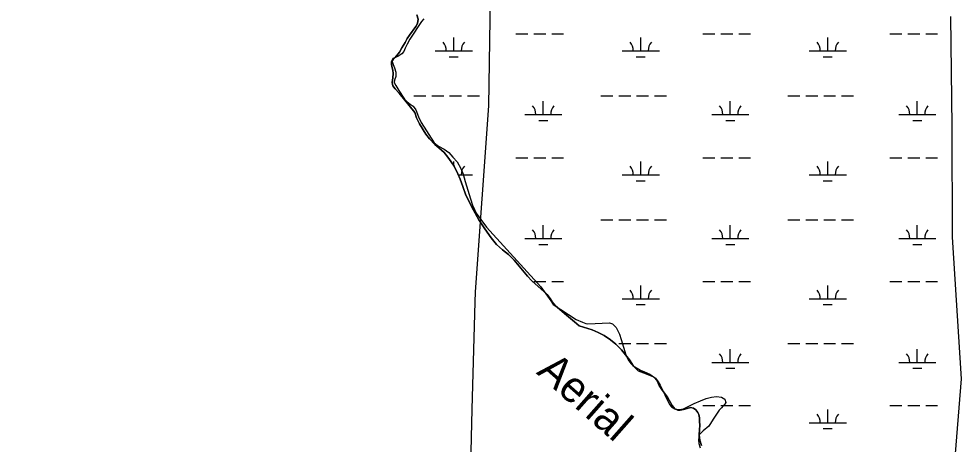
# Model space of a CAD drawing. Extents: x 3161564 to 3199464, y 849354 to 874788.
# Drawn here: x 3176490 to 3179019, y 859111 to 860252 of the extents above; entities that cross this region are included whole.
import ezdxf

# ---------------------------------------------------------------- set-up
doc = ezdxf.new("R2010")
doc.units = 0
for name, color, linetype in [('V-RIVR-IDEN', 7, 'Continuous'), ('V-ROAD-CNTR', 7, 'Continuous'), ('V-SITE-VEGE', 7, 'Continuous'), ('V-TOPO-BNDY', 7, 'Continuous'), ('V-TOPO-SHOR', 7, 'Continuous'), ('V-WETL-SWMP', 7, 'Continuous')]:
    doc.layers.add(name, color=color, linetype=linetype)

msp = doc.modelspace()

# ---------------------------------------------------------------- linework, layer by layer
at = {"layer": 'V-ROAD-CNTR'}
msp.add_spline([(3176879.1, 855651.9), (3176902.3, 855659.1), (3176934.1, 855667), (3176983.4, 855657.7), (3177040.7, 855639.1), (3177110.5, 855613.6), (3177170.6, 855601.8), (3177236.8, 855586.9), (3177274.8, 855573.5), (3177317.4, 855579.8), (3177362.6, 855595.7), (3177412, 855643.1), (3177451.7, 855679.2), (3177476.7, 855705.8), (3177478.3, 855737), (3177464.2, 855782.3), (3177430.8, 855833.4), (3177373, 855887.8), (3177287.8, 855954.8), (3177219.8, 855998.4), (3177153, 856039.4), (3177089.3, 856079.2), (3177023.4, 856134.3), (3176966.6, 856207.9), (3176895.2, 856290.1), (3176782.2, 856425.1), (3176693.2, 856545.3), (3176615.2, 856622.6), (3176543.9, 856726.5), (3176474.4, 856784.2), (3176414.4, 856823.6), (3176395.9, 856828), (3176350.8, 856806.2), (3176279.1, 856754.7), (3176211.6, 856707.4), (3176172.3, 856696.1), (3176141.1, 856702), (3176111.7, 856719.6), (3176032.6, 856777.4), (3175933.6, 856857.4), (3175839, 856930.3), (3175807.1, 856951.5), (3175770.1, 856958.7), (3175787.1, 856991.4), (3175795.1, 857040.7), (3175799.5, 857113.7), (3175810.8, 857206.9), (3175813.7, 857287.4), (3175807.8, 857386.8), (3175805.7, 857497.9), (3175801.9, 857543.6), (3175783.5, 857620.5), (3175760.2, 857716.1), (3175755.3, 857765.5), (3175754.5, 857815.6), (3175751.7, 857884.3), (3175756.3, 858015.5), (3175754.9, 858158.6), (3175753.1, 858270.8), (3175748.6, 858321.7), (3175736.5, 858372), (3175677.2, 858555.5), (3175602.2, 858747.1), (3175558.2, 858866.9), (3175502.5, 858986.2), (3175436.3, 859092.6), (3175371.2, 859185.1), (3175300.7, 859261.6), (3175219.1, 859367.2), (3175166.2, 859443.7), (3175175.3, 859507.1), (3175222, 859537.9), (3175285.3, 859568.3), (3175321.2, 859607.5), (3175310.3, 859667.2), (3175262.4, 859798.6), (3175224.6, 859877.9), (3175174.7, 859982), (3175144.8, 860115.4), (3175122.6, 860284.8), (3175088.4, 860568.6), (3175086.3, 860704.5), (3175072.2, 860854.5), (3175052.5, 860999.9), (3175047.5, 861166.8), (3175053.2, 861343.7), (3175066.7, 861550.4), (3175065.5, 861662.5), (3175040.2, 861767.8), (3175017.8, 861884.2), (3175008.4, 862033.9), (3174979.6, 862160.3), (3174952.1, 862274.6), (3174921.6, 862422.8), (3174897, 862525.5), (3174861.7, 862663.2), (3174841.1, 862738)], degree=3, dxfattribs=at)
at = {"layer": 'V-SITE-VEGE'}
for p, q in [((3177571.1, 860245.1), (3177540, 860197.8)), ((3177577.5, 860252.4), (3177571.1, 860245.1)), ((3177540, 860197.8), (3177532.6, 860184.6)), ((3177527.5, 860173.9), (3177523.8, 860164.9)), ((3177532.6, 860184.6), (3177527.5, 860173.9)), ((3177494.4, 860146.3), (3177491.7, 860140.8)), ((3177491.7, 860140.8), (3177494.8, 860129.8)), ((3177507.3, 860150.9), (3177494.4, 860146.3)), ((3177518.5, 860158.7), (3177507.3, 860150.9)), ((3177523.8, 860164.9), (3177518.5, 860158.7)), ((3177494.8, 860129.8), (3177498.7, 860120.6)), ((3177498.7, 860120.6), (3177502.1, 860109.3)), ((3177502, 860097.8), (3177498.1, 860087.4)), ((3177502.1, 860109.3), (3177502, 860097.8)), ((3177498.1, 860087.4), (3177497.5, 860081.7)), ((3177497.5, 860081.7), (3177501.7, 860073.7)), ((3177501.7, 860073.7), (3177510.3, 860060)), ((3177510.3, 860060), (3177525.8, 860037.2)), ((3177525.8, 860037.2), (3177532.3, 860030)), ((3177532.3, 860030), (3177540.4, 860023.6)), ((3177540.4, 860023.6), (3177548.2, 860018)), ((3177548.2, 860018), (3177555.5, 860007.8)), ((3177555.5, 860007.8), (3177562.9, 859989.1)), ((3177562.9, 859989.1), (3177569.9, 859974.2)), ((3177569.9, 859974.2), (3177605.1, 859920)), ((3177605.1, 859920), (3177616.2, 859910.8)), ((3177616.2, 859910.8), (3177631.7, 859902.9)), ((3177631.7, 859902.9), (3177644.6, 859893.3)), ((3177644.6, 859893.3), (3177655.3, 859881.5)), ((3177655.3, 859881.5), (3177666.5, 859868.6)), ((3177666.5, 859868.6), (3177676.7, 859850.8)), ((3177676.7, 859850.8), (3177682.7, 859835.4)), ((3177682.7, 859835.4), (3177688, 859816.1)), ((3177688, 859816.1), (3177702.7, 859769.4)), ((3177702.7, 859769.4), (3177708, 859752)), ((3177708, 859752), (3177712.9, 859740.6)), ((3177712.9, 859740.6), (3177717.6, 859730.9)), ((3177717.6, 859730.9), (3177745.9, 859693.1)), ((3177745.9, 859693.1), (3177891.2, 859533.3)), ((3177891.2, 859533.3), (3177918, 859495.9)), ((3177918, 859495.9), (3177924.6, 859485.6)), ((3177924.6, 859485.6), (3177986.4, 859445.7)), ((3177986.4, 859445.7), (3178002.8, 859438.7)), ((3178002.8, 859438.7), (3178012.5, 859434.7)), ((3178012.5, 859434.7), (3178017.7, 859433.4)), ((3178017.7, 859433.4), (3178075.5, 859436.2)), ((3178075.5, 859436.2), (3178083.7, 859433.9)), ((3178083.7, 859433.9), (3178093.6, 859424)), ((3178093.6, 859424), (3178102.5, 859406.3)), ((3178102.5, 859406.3), (3178107.2, 859391.7)), ((3178107.2, 859391.7), (3178119.4, 859351)), ((3178119.4, 859351), (3178125.6, 859337.3)), ((3178125.6, 859337.3), (3178132.7, 859327)), ((3178132.7, 859327), (3178139, 859320.8)), ((3178139, 859320.8), (3178158.7, 859309.1)), ((3178158.7, 859309.1), (3178169.7, 859305)), ((3178169.7, 859305), (3178183.5, 859298.9)), ((3178183.5, 859298.9), (3178198.8, 859288)), ((3178198.8, 859288), (3178206.4, 859277.9)), ((3178206.4, 859277.9), (3178211.5, 859269.3)), ((3178211.5, 859269.3), (3178236.7, 859217.1)), ((3178319.7, 859227.6), (3178334.9, 859233.3)), ((3178334.9, 859233.3), (3178349.5, 859237.3)), ((3178349.5, 859237.3), (3178362.4, 859238.6)), ((3178362.4, 859238.6), (3178375.8, 859237.2)), ((3178375.8, 859237.2), (3178385.6, 859231.7)), ((3178385.6, 859231.7), (3178387.5, 859222.7)), ((3178236.7, 859217.1), (3178242, 859211.2)), ((3178242, 859211.2), (3178250.9, 859205.8)), ((3178250.9, 859205.8), (3178262.6, 859203.7)), ((3178262.6, 859203.7), (3178273.8, 859205.3)), ((3178273.8, 859205.3), (3178302.5, 859219.9)), ((3178302.5, 859219.9), (3178319.7, 859227.6)), ((3178375.8, 859208.6), (3178370.3, 859202.2)), ((3178380.8, 859214.1), (3178375.8, 859208.6)), ((3178384.9, 859218.3), (3178380.8, 859214.1)), ((3178387.5, 859222.7), (3178384.9, 859218.3)), ((3178370.3, 859202.2), (3178353.7, 859178.1)), ((3178342.5, 859158.8), (3178327.4, 859146.8)), ((3178353.7, 859178.1), (3178342.5, 859158.8)), ((3178316.7, 859135.5), (3178314.3, 859122.3)), ((3178327.4, 859146.8), (3178316.7, 859135.5)), ((3178314.3, 859122.3), (3178315, 859112.3)), ((3178315, 859112.3), (3178319.1, 859101.1))]:
    msp.add_line(p, q, dxfattribs=at)
at = {"layer": 'V-TOPO-BNDY'}
for p, q in [((3177751.6, 860018.6), (3177757.6, 860399.3)), ((3177715.7, 859519.3), (3177751.6, 860018.6)), ((3177714.9, 859491.8), (3177715.7, 859519.3)), ((3177706.7, 859204.4), (3177714.9, 859491.8)), ((3177698.7, 858796.9), (3177706.7, 859204.4))]:
    msp.add_line(p, q, dxfattribs=at)
at = {"layer": 'V-TOPO-SHOR'}
for points in [[(3177558.4, 860263.6), (3177561.7, 860251.2), (3177560.3, 860239.7), (3177556, 860232.1), (3177539.2, 860208.5), (3177532.9, 860199.9), (3177527, 860188.8), (3177518, 860174.2), (3177511.8, 860162.6), (3177500.1, 860148.3), (3177494.9, 860143), (3177490.5, 860137.4), (3177490.1, 860130.9), (3177491, 860124.8), (3177493.9, 860115), (3177494.9, 860105.3), (3177494, 860093.9), (3177492.1, 860081.5), (3177494.3, 860072.9), (3177500.6, 860064.7), (3177511, 860052.8), (3177553.3, 860000.9), (3177557.8, 859986.7), (3177565.2, 859970.5), (3177582.9, 859943.3), (3177592.8, 859930.6), (3177606.9, 859915.4), (3177617.3, 859906), (3177625.1, 859899.9), (3177631.7, 859894.1), (3177642.1, 859881.1), (3177650.8, 859868.4), (3177658.4, 859856.9), (3177668.5, 859836), (3177674.4, 859821.8), (3177681.6, 859802.3), (3177689.9, 859779), (3177710.8, 859738.5), (3177724.6, 859712.7), (3177741.4, 859689.2), (3177758.2, 859664.5), (3177772.6, 859647.1), (3177788.2, 859632.3)], [(3177788.2, 859632.3), (3177804.4, 859619.8), (3177819.5, 859605.1), (3177855.1, 859562.1), (3177867.3, 859549.4), (3177908, 859513), (3177916.4, 859502.1), (3177921.7, 859493.1), (3177930.1, 859483.2), (3177942.3, 859472.1), (3177960.3, 859457.5), (3177981.9, 859439.1), (3177993.9, 859428.7), (3178028.7, 859417.3), (3178045.2, 859410.9), (3178061, 859402.2), (3178078.7, 859390.6), (3178092.6, 859379.2), (3178107.9, 859364.2), (3178129.1, 859337.6), (3178140.4, 859320.3), (3178152.9, 859308.1), (3178174.1, 859299.2), (3178193.5, 859292), (3178203.8, 859280.8), (3178208.8, 859268.3), (3178217.7, 859254.5), (3178231.1, 859236.8), (3178243.6, 859214.8), (3178251.2, 859205.9), (3178258.9, 859201.7), (3178265.1, 859202.2), (3178274.6, 859204), (3178284.5, 859206.7), (3178293.3, 859208.9), (3178301.3, 859207.7), (3178307.3, 859203.4), (3178312.7, 859195.5), (3178315.1, 859190.9), (3178317, 859181.4), (3178317, 859171.4), (3178318.1, 859162.1), (3178317, 859149.3), (3178316.7, 859136.2), (3178318.5, 859122), (3178322.5, 859106.9)]]:
    msp.add_lwpolyline(points, dxfattribs=at)
at = {"layer": 'V-WETL-SWMP'}
for p, q in [((3177561.7, 860251.2), (3177558.4, 860263.6)), ((3177560.3, 860239.7), (3177561.7, 860251.2)), ((3178991, 860258.3), (3178994.1, 859963.6)), ((3177539.2, 860208.5), (3177556, 860232.1)), ((3177556, 860232.1), (3177560.3, 860239.7)), ((3177527, 860188.8), (3177532.9, 860199.9)), ((3177532.9, 860199.9), (3177539.2, 860208.5)), ((3177657.5, 860166.1), (3177657.5, 860202.1)), ((3177824.5, 860212.5), (3177856.5, 860212.5)), ((3177872.5, 860212.5), (3177904.5, 860212.5)), ((3177920.5, 860212.5), (3177952.5, 860212.5)), ((3178159.4, 860166.1), (3178159.4, 860202.1)), ((3178326.5, 860212.5), (3178358.5, 860212.5)), ((3178374.5, 860212.5), (3178406.5, 860212.5)), ((3178422.5, 860212.5), (3178454.5, 860212.5)), ((3178661.3, 860166.1), (3178661.3, 860202.1)), ((3178828.4, 860212.5), (3178860.4, 860212.5)), ((3178876.4, 860212.5), (3178908.4, 860212.5)), ((3178924.4, 860212.5), (3178956.4, 860212.5)), ((3177511.8, 860162.6), (3177518, 860174.2)), ((3177518, 860174.2), (3177527, 860188.8)), ((3177607.5, 860166.1), (3177707.5, 860166.1)), ((3178109.4, 860166.1), (3178209.4, 860166.1)), ((3178611.3, 860166.1), (3178711.3, 860166.1)), ((3177490.5, 860137.4), (3177494.9, 860143)), ((3177494.9, 860143), (3177500.1, 860148.3)), ((3177500.1, 860148.3), (3177511.8, 860162.6)), ((3177645.5, 860150.7), (3177669.5, 860150.7)), ((3178147.4, 860150.7), (3178171.4, 860150.7)), ((3178649.3, 860150.7), (3178673.3, 860150.7)), ((3177490.1, 860130.9), (3177490.5, 860137.4)), ((3177491, 860124.8), (3177490.1, 860130.9)), ((3177493.9, 860115), (3177491, 860124.8)), ((3177494.9, 860105.3), (3177493.9, 860115)), ((3177492.1, 860081.5), (3177494, 860093.9)), ((3177494, 860093.9), (3177494.9, 860105.3)), ((3177494.3, 860072.9), (3177492.1, 860081.5)), ((3177500.6, 860064.7), (3177494.3, 860072.9)), ((3177511, 860052.8), (3177500.6, 860064.7)), ((3177553.3, 860000.9), (3177511, 860052.8)), ((3177550.6, 860046), (3177582.6, 860046)), ((3177598.6, 860046), (3177630.6, 860046)), ((3177646.6, 860046), (3177678.6, 860046)), ((3177694.6, 860046), (3177726.6, 860046)), ((3178052.5, 860046), (3178084.5, 860046)), ((3178100.5, 860046), (3178132.5, 860046)), ((3178148.5, 860046), (3178180.5, 860046)), ((3178196.5, 860046), (3178228.5, 860046)), ((3178554.5, 860046), (3178586.5, 860046)), ((3178602.5, 860046), (3178634.5, 860046)), ((3178650.5, 860046), (3178682.5, 860046)), ((3178698.5, 860046), (3178730.5, 860046)), ((3177898, 859995.3), (3177898, 860031.3)), ((3178399.9, 859995.3), (3178399.9, 860031.3)), ((3178901.8, 859995.3), (3178901.8, 860031.3)), ((3177557.8, 859986.7), (3177553.3, 860000.9)), ((3177848, 859995.3), (3177948, 859995.3)), ((3178349.9, 859995.3), (3178449.9, 859995.3)), ((3178851.8, 859995.3), (3178951.8, 859995.3)), ((3177565.2, 859970.5), (3177557.8, 859986.7)), ((3177582.9, 859943.3), (3177565.2, 859970.5)), ((3177886, 859979.8), (3177910, 859979.8)), ((3178387.9, 859979.8), (3178411.9, 859979.8)), ((3178889.8, 859979.8), (3178913.8, 859979.8)), ((3178994.1, 859963.6), (3178995.4, 859666.4)), ((3177592.8, 859930.6), (3177582.9, 859943.3)), ((3177606.9, 859915.4), (3177592.8, 859930.6)), ((3177617.3, 859906), (3177606.9, 859915.4)), ((3177625.1, 859899.9), (3177617.3, 859906)), ((3177631.7, 859894.1), (3177625.1, 859899.9)), ((3177642.1, 859881.1), (3177631.7, 859894.1)), ((3177650.8, 859868.4), (3177642.1, 859881.1)), ((3177658.4, 859856.9), (3177650.8, 859868.4)), ((3177657.5, 859858.2), (3177657.5, 859869.4)), ((3177824.5, 859879.8), (3177856.5, 859879.8)), ((3177872.5, 859879.8), (3177904.5, 859879.8)), ((3177920.5, 859879.8), (3177952.5, 859879.8)), ((3178159.4, 859833.4), (3178159.4, 859869.4)), ((3178326.5, 859879.8), (3178358.5, 859879.8)), ((3178374.5, 859879.8), (3178406.5, 859879.8)), ((3178422.5, 859879.8), (3178454.5, 859879.8)), ((3178661.3, 859833.4), (3178661.3, 859869.4)), ((3178828.4, 859879.8), (3178860.4, 859879.8)), ((3178876.4, 859879.8), (3178908.4, 859879.8)), ((3178924.4, 859879.8), (3178956.4, 859879.8)), ((3177668.5, 859836), (3177658.4, 859856.9)), ((3177674.4, 859821.8), (3177668.5, 859836)), ((3177669.6, 859833.4), (3177707.5, 859833.4)), ((3177681.6, 859802.3), (3177674.4, 859821.8)), ((3178109.4, 859833.4), (3178209.4, 859833.4)), ((3178147.4, 859818), (3178171.4, 859818)), ((3178611.3, 859833.4), (3178711.3, 859833.4)), ((3178649.3, 859818), (3178673.3, 859818)), ((3177689.9, 859779), (3177681.6, 859802.3)), ((3177710.8, 859738.5), (3177689.9, 859779)), ((3177724.6, 859712.7), (3177710.8, 859738.5)), ((3177724.3, 859713.3), (3177726.6, 859713.3)), ((3177741.4, 859689.2), (3177724.6, 859712.7)), ((3178052.5, 859713.3), (3178084.5, 859713.3)), ((3178100.5, 859713.3), (3178132.5, 859713.3)), ((3178148.5, 859713.3), (3178180.5, 859713.3)), ((3178196.5, 859713.3), (3178228.5, 859713.3)), ((3178554.5, 859713.3), (3178586.5, 859713.3)), ((3178602.5, 859713.3), (3178634.5, 859713.3)), ((3178650.5, 859713.3), (3178682.5, 859713.3)), ((3178698.5, 859713.3), (3178730.5, 859713.3)), ((3177758.2, 859664.5), (3177741.4, 859689.2)), ((3177898, 859662.6), (3177898, 859698.6)), ((3178399.9, 859662.6), (3178399.9, 859698.6)), ((3178901.8, 859662.6), (3178901.8, 859698.6)), ((3177772.6, 859647.1), (3177758.2, 859664.5)), ((3177848, 859662.6), (3177948, 859662.6)), ((3178349.9, 859662.6), (3178449.9, 859662.6)), ((3178851.8, 859662.6), (3178951.8, 859662.6)), ((3178995.4, 859666.4), (3179019.5, 859286.4)), ((3177788.2, 859632.3), (3177772.6, 859647.1)), ((3177886, 859647.2), (3177910, 859647.2)), ((3178387.9, 859647.2), (3178411.9, 859647.2)), ((3178889.8, 859647.2), (3178913.8, 859647.2)), ((3177804.4, 859619.8), (3177788.2, 859632.3)), ((3177819.5, 859605.1), (3177804.4, 859619.8)), ((3177855.1, 859562.1), (3177819.5, 859605.1)), ((3177867.3, 859549.4), (3177855.1, 859562.1)), ((3177908, 859513), (3177867.3, 859549.4)), ((3177872.5, 859547.2), (3177904.5, 859547.2)), ((3177920.5, 859547.2), (3177952.5, 859547.2)), ((3178159.4, 859500.7), (3178159.4, 859536.7)), ((3178326.5, 859547.2), (3178358.5, 859547.2)), ((3178374.5, 859547.2), (3178406.5, 859547.2)), ((3178422.5, 859547.2), (3178454.5, 859547.2)), ((3178661.3, 859500.7), (3178661.3, 859536.7)), ((3178828.4, 859547.2), (3178860.4, 859547.2)), ((3178876.4, 859547.2), (3178908.4, 859547.2)), ((3178924.4, 859547.2), (3178956.4, 859547.2)), ((3177916.4, 859502.1), (3177908, 859513)), ((3177921.7, 859493.1), (3177916.4, 859502.1)), ((3177930.1, 859483.2), (3177921.7, 859493.1)), ((3177942.3, 859472.1), (3177930.1, 859483.2)), ((3178109.4, 859500.7), (3178209.4, 859500.7)), ((3178147.4, 859485.3), (3178171.4, 859485.3)), ((3178611.3, 859500.7), (3178711.3, 859500.7)), ((3178649.3, 859485.3), (3178673.3, 859485.3)), ((3177960.3, 859457.5), (3177942.3, 859472.1)), ((3177981.9, 859439.1), (3177960.3, 859457.5)), ((3177993.9, 859428.7), (3177981.9, 859439.1)), ((3178028.7, 859417.3), (3177993.9, 859428.7)), ((3178045.2, 859410.9), (3178028.7, 859417.3)), ((3178061, 859402.2), (3178045.2, 859410.9)), ((3178078.7, 859390.6), (3178061, 859402.2)), ((3178092.7, 859379.2), (3178078.7, 859390.6)), ((3178107.9, 859364.2), (3178092.7, 859379.2)), ((3178100.5, 859380.7), (3178132.5, 859380.7)), ((3178129.1, 859337.6), (3178107.9, 859364.2)), ((3178148.5, 859380.7), (3178180.5, 859380.7)), ((3178196.5, 859380.7), (3178228.5, 859380.7)), ((3178399.9, 859329.9), (3178399.9, 859365.9)), ((3178554.5, 859380.7), (3178586.5, 859380.7)), ((3178602.5, 859380.7), (3178634.5, 859380.7)), ((3178650.5, 859380.7), (3178682.5, 859380.7)), ((3178698.5, 859380.7), (3178730.5, 859380.7)), ((3178901.8, 859329.9), (3178901.8, 859365.9)), ((3178140.4, 859320.3), (3178129.1, 859337.6)), ((3178152.9, 859308.1), (3178140.4, 859320.3)), ((3178174.1, 859299.2), (3178152.9, 859308.1)), ((3178349.9, 859329.9), (3178449.9, 859329.9)), ((3178387.9, 859314.5), (3178411.9, 859314.5)), ((3178851.8, 859329.9), (3178951.8, 859329.9)), ((3178889.8, 859314.5), (3178913.8, 859314.5)), ((3178193.5, 859292), (3178174.1, 859299.2)), ((3178203.8, 859280.8), (3178193.5, 859292)), ((3178208.8, 859268.3), (3178203.8, 859280.8)), ((3179019.5, 859286.4), (3178987.5, 858881.9)), ((3178217.7, 859254.5), (3178208.8, 859268.3)), ((3178231.1, 859236.8), (3178217.7, 859254.5)), ((3178243.6, 859214.8), (3178231.1, 859236.8)), ((3178251.2, 859205.9), (3178243.6, 859214.8)), ((3178258.9, 859201.7), (3178251.2, 859205.9)), ((3178284.5, 859206.7), (3178274.6, 859204)), ((3178293.3, 859208.9), (3178284.5, 859206.7)), ((3178301.3, 859207.7), (3178293.3, 859208.9)), ((3178307.4, 859203.4), (3178301.3, 859207.7)), ((3178326.5, 859214.5), (3178358.5, 859214.5)), ((3178374.5, 859214.5), (3178406.5, 859214.5)), ((3178422.5, 859214.5), (3178454.5, 859214.5)), ((3178828.4, 859214.5), (3178860.4, 859214.5)), ((3178876.4, 859214.5), (3178908.4, 859214.5)), ((3178924.4, 859214.5), (3178956.4, 859214.5)), ((3178265.1, 859202.2), (3178258.9, 859201.7)), ((3178274.6, 859204), (3178265.1, 859202.2)), ((3178312.7, 859195.5), (3178307.4, 859203.4)), ((3178315.1, 859190.9), (3178312.7, 859195.5)), ((3178317, 859181.4), (3178315.1, 859190.9)), ((3178317, 859171.4), (3178317, 859181.4)), ((3178661.3, 859168.1), (3178661.3, 859204.1)), ((3178318.1, 859162.1), (3178317, 859171.4)), ((3178317, 859149.3), (3178318.1, 859162.1)), ((3178611.3, 859168.1), (3178711.3, 859168.1)), ((3178316.7, 859136.2), (3178317, 859149.3)), ((3178318.5, 859122), (3178316.7, 859136.2)), ((3178649.3, 859152.6), (3178673.3, 859152.6)), ((3178322.5, 859106.9), (3178318.5, 859122))]:
    msp.add_line(p, q, dxfattribs=at)
for centre, start, end in [((3177602.2, 860166.6), 359.2282, 40.7718), ((3177712.7, 860166.6), 139.2282, 180.7718), ((3178104.1, 860166.6), 359.2282, 40.7718), ((3178214.6, 860166.6), 139.2282, 180.7718), ((3178606.1, 860166.6), 359.2282, 40.7718), ((3178716.5, 860166.6), 139.2282, 180.7718), ((3177842.7, 859995.8), 359.2282, 40.7718), ((3177953.2, 859995.8), 139.2282, 180.7718), ((3178344.6, 859995.8), 359.2282, 40.7718), ((3178455.1, 859995.8), 139.2282, 180.7718), ((3178846.5, 859995.8), 359.2282, 40.7718), ((3178957, 859995.8), 139.2282, 180.7718), ((3177712.7, 859833.9), 139.2282, 180.7718), ((3178104.1, 859833.9), 359.2282, 40.7718), ((3178214.6, 859833.9), 139.2282, 180.7718), ((3178606.1, 859833.9), 359.2282, 40.7718), ((3178716.5, 859833.9), 139.2282, 180.7718), ((3177842.7, 859663.1), 359.2282, 40.7718), ((3177953.2, 859663.1), 139.2282, 180.7718), ((3178344.6, 859663.1), 359.2282, 40.7718), ((3178455.1, 859663.1), 139.2282, 180.7718), ((3178846.5, 859663.1), 359.2282, 40.7718), ((3178957, 859663.1), 139.2282, 180.7718), ((3178104.1, 859501.2), 359.2282, 40.7718), ((3178214.6, 859501.2), 139.2282, 180.7718), ((3178606.1, 859501.2), 359.2282, 40.7718), ((3178716.5, 859501.2), 139.2282, 180.7718), ((3178344.6, 859330.4), 359.2282, 40.7718), ((3178455.1, 859330.4), 139.2282, 180.7718), ((3178846.5, 859330.4), 359.2282, 40.7718), ((3178957, 859330.4), 139.2282, 180.7718), ((3178606.1, 859168.5), 359.2282, 40.7718), ((3178716.5, 859168.5), 139.2282, 180.7718)]:
    msp.add_arc(centre, 35.2, start, end, dxfattribs=at)

# ---------------------------------------------------------------- texts
at = {"layer": 'V-RIVR-IDEN'}
msp.add_text('Aerial', height=83, rotation=318.5671, dxfattribs=at).set_placement((3177877.3, 859301.5))

doc.saveas('drawing.dxf')
